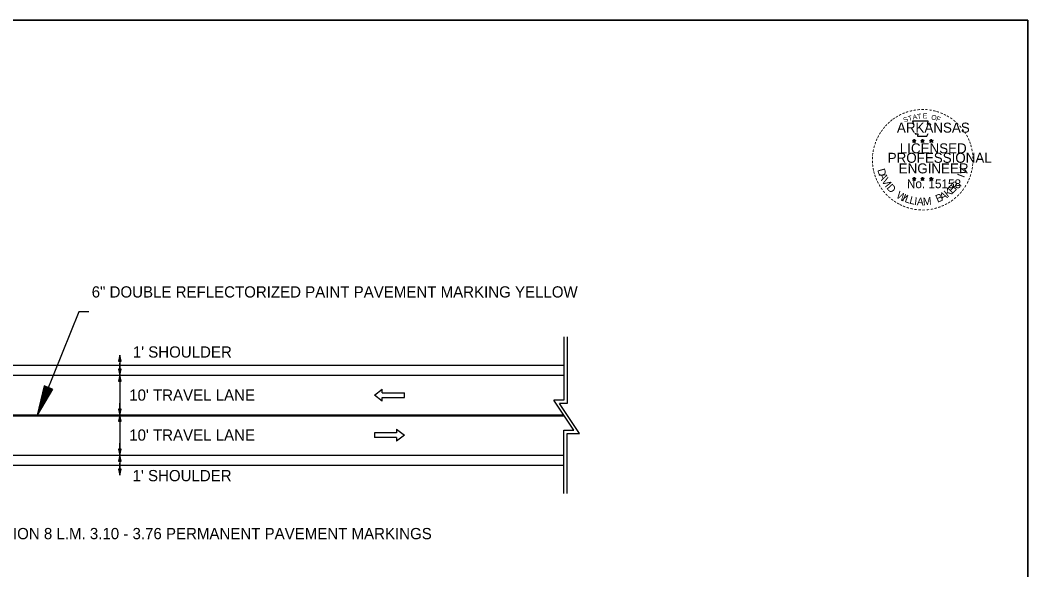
# Model space of a CAD drawing. Extents: x 1372926 to 1373096, y 381240 to 381790.
# Drawn here: x 1372995.2 to 1373096, y 381515.2 to 381570.2 of the extents above; entities that cross this region are included whole.
import ezdxf

# ---------------------------------------------------------------- set-up
doc = ezdxf.new("R2010")
doc.units = 0
for name, color, linetype in [('Default', 7, 'Continuous'), ('DSN_DRFT_Junk-No-Plot', 7, 'Continuous'), ('R_Draft', 7, 'Continuous'), ('SHET_Border-Text', 7, 'Continuous')]:
    doc.layers.add(name, color=color, linetype=linetype)

msp = doc.modelspace()

# ---------------------------------------------------------------- linework, layer by layer
at = {"layer": 'Default'}
for p, q in [((1373001.06, 381541), (1372996.9, 381530.64)), ((1373002.06, 381541), (1373001.06, 381541)), ((1373049.57, 381538.48), (1373049.57, 381532.14)), ((1373049.91, 381538.48), (1373049.91, 381531.81)), ((1372997.6, 381533.6), (1372996.9, 381530.64)), ((1372998.44, 381533.26), (1372996.9, 381530.64)), ((1372997.67, 381533.57), (1372997.09, 381531.11)), ((1372998.37, 381533.29), (1372997.09, 381531.11)), ((1372997.75, 381533.54), (1372997.28, 381531.59)), ((1372998.3, 381533.32), (1372997.28, 381531.59)), ((1372997.82, 381533.51), (1372997.47, 381532.05)), ((1372998.23, 381533.35), (1372997.47, 381532.05)), ((1372998.44, 381533.26), (1372997.6, 381533.6)), ((1372997.89, 381533.48), (1372997.66, 381532.52)), ((1372998.16, 381533.37), (1372997.66, 381532.52)), ((1372997.96, 381533.46), (1372997.85, 381532.99)), ((1372998.09, 381533.4), (1372997.85, 381532.99)), ((1373030.65, 381532.64), (1373031.42, 381533.24)), ((1373031.42, 381532.04), (1373030.65, 381532.64)), ((1373031.42, 381532.87), (1373031.42, 381533.24)), ((1373031.42, 381532.87), (1373033.63, 381532.87)), ((1373033.63, 381532.42), (1373033.63, 381532.87)), ((1373031.42, 381532.42), (1373033.63, 381532.42)), ((1373031.42, 381532.04), (1373031.42, 381532.42)), ((1373049.57, 381532.14), (1373048.57, 381532.14)), ((1373050.57, 381529.14), (1373048.57, 381532.14)), ((1373051.13, 381528.81), (1373049.13, 381531.81)), ((1373049.91, 381531.81), (1373049.13, 381531.81)), ((1373032.85, 381528.87), (1373030.65, 381528.87)), ((1373030.65, 381528.87), (1373030.65, 381528.42)), ((1373032.85, 381529.24), (1373032.85, 381528.87)), ((1373032.85, 381529.24), (1373033.63, 381528.64)), ((1373033.63, 381528.64), (1373032.85, 381528.04)), ((1373049.57, 381522.81), (1373049.57, 381529.14)), ((1373049.57, 381529.14), (1373050.57, 381529.14)), ((1373049.91, 381522.81), (1373049.91, 381528.81)), ((1373049.91, 381528.81), (1373051.13, 381528.81)), ((1373032.85, 381528.42), (1373030.65, 381528.42)), ((1373032.85, 381528.42), (1373032.85, 381528.04))]:
    msp.add_line(p, q, dxfattribs=at)
msp.add_lwpolyline([(1372925.97, 381570.17), (1372925.97, 381460.17), (1373095.97, 381460.17), (1373095.97, 381570.17)], close=True, dxfattribs=at)
at = {"layer": 'DSN_DRFT_Junk-No-Plot'}
msp.add_line((1373005.17, 381536.64), (1373005.17, 381524.64), dxfattribs=at)
for points in [[(1372925.97, 381570.17), (1373095.97, 381570.17), (1373095.97, 381460.17), (1372925.97, 381460.17)], [(1372925.97, 381570.17), (1372925.97, 381460.17), (1373095.97, 381460.17), (1373095.97, 381570.17)]]:
    msp.add_lwpolyline(points, close=True, dxfattribs=at)
for points in [[(1373005.17, 381536.64), (1373005.05, 381536.04), (1373005.29, 381536.04), (1373005.17, 381536.64), (1373005.17, 381535.44)], [(1373005.17, 381534.64), (1373005.29, 381535.24), (1373005.05, 381535.24), (1373005.17, 381534.64), (1373005.17, 381535.84)], [(1373005.17, 381534.64), (1373005.05, 381534.04), (1373005.29, 381534.04), (1373005.17, 381534.64), (1373005.17, 381533.44)], [(1373005.17, 381530.64), (1373005.29, 381531.24), (1373005.05, 381531.24), (1373005.17, 381530.64), (1373005.17, 381531.84)], [(1373005.17, 381530.64), (1373005.05, 381530.04), (1373005.29, 381530.04), (1373005.17, 381530.64), (1373005.17, 381529.44)], [(1373005.17, 381526.64), (1373005.29, 381527.24), (1373005.05, 381527.24), (1373005.17, 381526.64), (1373005.17, 381527.84)], [(1373005.17, 381526.64), (1373005.05, 381526.04), (1373005.29, 381526.04), (1373005.17, 381526.64), (1373005.17, 381525.44)], [(1373005.17, 381524.64), (1373005.29, 381525.24), (1373005.05, 381525.24), (1373005.17, 381524.64), (1373005.17, 381525.84)]]:
    msp.add_lwpolyline(points, dxfattribs=at)
at = {"layer": 'R_Draft'}
for p, q in [((1372973.18, 381535.64), (1373049.57, 381535.64)), ((1372973.18, 381534.64), (1373049.57, 381534.64)), ((1372973.15, 381530.69), (1373049.54, 381530.69)), ((1372973.21, 381530.59), (1373049.61, 381530.59)), ((1372973.18, 381526.64), (1373049.57, 381526.64)), ((1372973.18, 381525.64), (1373049.57, 381525.64))]:
    msp.add_line(p, q, dxfattribs=at)
at = {"layer": 'SHET_Border-Text'}
for p, q in [((1373084.43, 381558.13), (1373084.6, 381558.07)), ((1373084.43, 381558.13), (1373084.56, 381558.11)), ((1373084.43, 381558.13), (1373084.55, 381558.07)), ((1373084.5, 381557.93), (1373084.6, 381558.07)), ((1373084.5, 381557.93), (1373084.56, 381558.05)), ((1373084.5, 381557.93), (1373084.6, 381558.03)), ((1373084.6, 381558.26), (1373084.58, 381558.13)), ((1373084.6, 381558.07), (1373084.6, 381558.26)), ((1373084.6, 381558.26), (1373084.63, 381558.13)), ((1373084.78, 381558.13), (1373084.6, 381558.07)), ((1373084.71, 381557.93), (1373084.6, 381558.07)), ((1373084.71, 381557.93), (1373084.6, 381558.03)), ((1373084.78, 381558.13), (1373084.63, 381558.11)), ((1373084.71, 381557.93), (1373084.64, 381558.07)), ((1373084.78, 381558.13), (1373084.67, 381558.08)), ((1373085.26, 381558.13), (1373085.44, 381558.07)), ((1373085.26, 381558.13), (1373085.39, 381558.11)), ((1373085.26, 381558.13), (1373085.38, 381558.07)), ((1373085.33, 381557.93), (1373085.44, 381558.07)), ((1373085.33, 381557.93), (1373085.39, 381558.05)), ((1373085.33, 381557.93), (1373085.44, 381558.03)), ((1373085.44, 381558.26), (1373085.42, 381558.13)), ((1373085.44, 381558.07), (1373085.44, 381558.26)), ((1373085.44, 381558.26), (1373085.46, 381558.13)), ((1373085.61, 381558.13), (1373085.44, 381558.07)), ((1373085.54, 381557.93), (1373085.44, 381558.07)), ((1373085.54, 381557.93), (1373085.44, 381558.03)), ((1373085.61, 381558.13), (1373085.47, 381558.11)), ((1373085.54, 381557.93), (1373085.48, 381558.07)), ((1373085.61, 381558.13), (1373085.51, 381558.08)), ((1373086.15, 381558.12), (1373086.32, 381558.07)), ((1373086.15, 381558.12), (1373086.27, 381558.1)), ((1373086.15, 381558.12), (1373086.26, 381558.06)), ((1373086.21, 381557.92), (1373086.32, 381558.07)), ((1373086.21, 381557.92), (1373086.28, 381558.04)), ((1373086.21, 381557.92), (1373086.32, 381558.03)), ((1373086.32, 381558.25), (1373086.3, 381558.12)), ((1373086.32, 381558.07), (1373086.32, 381558.25)), ((1373086.32, 381558.25), (1373086.34, 381558.13)), ((1373086.49, 381558.12), (1373086.32, 381558.07)), ((1373086.43, 381557.92), (1373086.32, 381558.07)), ((1373086.43, 381557.92), (1373086.32, 381558.03)), ((1373086.49, 381558.12), (1373086.35, 381558.1)), ((1373086.43, 381557.92), (1373086.36, 381558.07)), ((1373086.49, 381558.12), (1373086.39, 381558.07)), ((1373084.43, 381554.34), (1373084.6, 381554.29)), ((1373084.43, 381554.34), (1373084.55, 381554.32)), ((1373084.43, 381554.34), (1373084.55, 381554.28)), ((1373084.49, 381554.14), (1373084.6, 381554.29)), ((1373084.49, 381554.14), (1373084.56, 381554.26)), ((1373084.49, 381554.14), (1373084.6, 381554.25)), ((1373084.6, 381554.47), (1373084.58, 381554.34)), ((1373084.6, 381554.29), (1373084.6, 381554.47)), ((1373084.6, 381554.47), (1373084.63, 381554.35)), ((1373084.77, 381554.34), (1373084.6, 381554.29)), ((1373084.71, 381554.14), (1373084.6, 381554.29)), ((1373084.71, 381554.14), (1373084.6, 381554.25)), ((1373084.77, 381554.34), (1373084.63, 381554.32)), ((1373084.71, 381554.14), (1373084.64, 381554.28)), ((1373084.77, 381554.34), (1373084.67, 381554.29)), ((1373085.26, 381554.34), (1373085.44, 381554.29)), ((1373085.26, 381554.34), (1373085.39, 381554.32)), ((1373085.26, 381554.34), (1373085.38, 381554.28)), ((1373085.33, 381554.14), (1373085.44, 381554.29)), ((1373085.33, 381554.14), (1373085.39, 381554.26)), ((1373085.33, 381554.14), (1373085.43, 381554.25)), ((1373085.44, 381554.47), (1373085.42, 381554.34)), ((1373085.54, 381554.14), (1373085.43, 381554.25)), ((1373085.44, 381554.29), (1373085.44, 381554.47)), ((1373085.44, 381554.47), (1373085.46, 381554.35)), ((1373085.61, 381554.34), (1373085.44, 381554.29)), ((1373085.54, 381554.14), (1373085.44, 381554.29)), ((1373085.61, 381554.34), (1373085.47, 381554.32)), ((1373085.54, 381554.14), (1373085.47, 381554.28)), ((1373085.61, 381554.34), (1373085.51, 381554.29)), ((1373086.14, 381554.34), (1373086.32, 381554.28)), ((1373086.14, 381554.34), (1373086.27, 381554.32)), ((1373086.14, 381554.34), (1373086.26, 381554.28)), ((1373086.21, 381554.13), (1373086.32, 381554.28)), ((1373086.21, 381554.13), (1373086.27, 381554.26)), ((1373086.21, 381554.13), (1373086.32, 381554.24)), ((1373086.32, 381554.47), (1373086.3, 381554.34)), ((1373086.32, 381554.28), (1373086.32, 381554.47)), ((1373086.32, 381554.47), (1373086.34, 381554.34)), ((1373086.49, 381554.34), (1373086.32, 381554.28)), ((1373086.43, 381554.13), (1373086.32, 381554.28)), ((1373086.43, 381554.13), (1373086.32, 381554.24)), ((1373086.49, 381554.34), (1373086.35, 381554.31)), ((1373086.43, 381554.13), (1373086.36, 381554.28)), ((1373086.49, 381554.34), (1373086.39, 381554.29))]:
    msp.add_line(p, q, dxfattribs=at)
for points in [[(1373084.45, 381560.07), (1373084.58, 381559.66)], [(1373086.2, 381559.61), (1373086.28, 381559.75), (1373085.93, 381559.74), (1373086.01, 381560.07), (1373084.45, 381560.07)], [(1373084.7, 381558.86), (1373084.7, 381558.81), (1373084.98, 381558.8), (1373084.95, 381558.57), (1373085.88, 381558.57), (1373085.99, 381558.84)], [(1373084.6, 381558.26), (1373084.71, 381557.93), (1373084.43, 381558.13), (1373084.78, 381558.13), (1373084.5, 381557.93), (1373084.6, 381558.26)], [(1373085.44, 381558.26), (1373085.54, 381557.93), (1373085.26, 381558.13), (1373085.61, 381558.13), (1373085.33, 381557.93), (1373085.44, 381558.26)], [(1373086.32, 381558.25), (1373086.43, 381557.92), (1373086.15, 381558.12), (1373086.49, 381558.12), (1373086.21, 381557.92), (1373086.32, 381558.25)], [(1373084.6, 381554.47), (1373084.71, 381554.14), (1373084.43, 381554.34), (1373084.77, 381554.34), (1373084.49, 381554.14), (1373084.6, 381554.47)], [(1373085.44, 381554.47), (1373085.54, 381554.14), (1373085.26, 381554.34), (1373085.61, 381554.34), (1373085.33, 381554.14), (1373085.44, 381554.47)], [(1373086.32, 381554.47), (1373086.43, 381554.13), (1373086.14, 381554.34), (1373086.49, 381554.34), (1373086.21, 381554.13), (1373086.32, 381554.47)]]:
    msp.add_lwpolyline(points, dxfattribs=at)
for centre, radius in [((1373084.6, 381558.07), 0.0861), ((1373084.6, 381558.07), 0.0723), ((1373084.6, 381558.07), 0.0579), ((1373084.6, 381558.07), 0.0495), ((1373084.6, 381558.07), 0.0374), ((1373084.6, 381558.07), 0.0248), ((1373084.6, 381558.07), 0.0148), ((1373085.44, 381558.07), 0.0861), ((1373085.44, 381558.07), 0.0723), ((1373085.44, 381558.07), 0.0579), ((1373085.44, 381558.07), 0.0495), ((1373085.44, 381558.07), 0.0374), ((1373085.44, 381558.07), 0.0248), ((1373085.44, 381558.07), 0.0148), ((1373086.32, 381558.07), 0.0861), ((1373086.32, 381558.07), 0.0723), ((1373086.32, 381558.07), 0.0579), ((1373086.32, 381558.07), 0.0495), ((1373086.32, 381558.07), 0.0374), ((1373086.32, 381558.07), 0.0248), ((1373086.32, 381558.07), 0.0148), ((1373084.6, 381554.29), 0.0861), ((1373084.6, 381554.29), 0.0723), ((1373084.6, 381554.29), 0.0579), ((1373084.6, 381554.29), 0.0495), ((1373084.6, 381554.29), 0.0374), ((1373084.6, 381554.29), 0.0248), ((1373084.6, 381554.29), 0.0148), ((1373085.44, 381554.29), 0.0861), ((1373085.44, 381554.29), 0.0723), ((1373085.44, 381554.29), 0.0579), ((1373085.44, 381554.29), 0.0495), ((1373085.44, 381554.29), 0.0374), ((1373085.44, 381554.29), 0.0248), ((1373085.44, 381554.29), 0.0148), ((1373086.32, 381554.28), 0.0861), ((1373086.32, 381554.28), 0.0723), ((1373086.32, 381554.28), 0.0579), ((1373086.32, 381554.28), 0.0495), ((1373086.32, 381554.28), 0.0374), ((1373086.32, 381554.28), 0.0248), ((1373086.32, 381554.28), 0.0148)]:
    msp.add_circle(centre, radius, dxfattribs=at)

# ---------------------------------------------------------------- texts
at = {"layer": 'Default'}
msp.add_text('6" DOUBLE REFLECTORIZED PAINT PAVEMENT MARKING YELLOW', height=1.125, dxfattribs=at).set_placement((1373002.36, 381542.42))
at = {"layer": 'R_Draft'}
for s, p in [("1' SHOULDER", (1373006.47, 381536.41)), ("10' TRAVEL LANE", (1373006.11, 381532.1)), ("10' TRAVEL LANE", (1373006.11, 381528.1)), ("1' SHOULDER", (1373006.45, 381524.04)), ('HWY. 128 SECTION 8 L.M. 3.10 - 3.76 PERMANENT PAVEMENT MARKINGS', (1372983.2, 381518.24))]:
    msp.add_text(s, height=1.125, dxfattribs=at).set_placement(p)
at = {"layer": 'SHET_Border-Text'}
for s, height, rotation, p in [('-', 0.8, 24.3072, (1373083.51, 381560.5)), ('-', 0.8, 19.1761, (1373083.82, 381560.63)), ('-', 0.8, 13.6302, (1373084.2, 381560.75)), ('-', 0.8, 10.2193, (1373084.54, 381560.83)), ('-', 0.8, 5.8968, (1373084.9, 381560.89)), ('-', 0.8, 0.1862, (1373085.29, 381560.92)), ('E', 0.5, 0.8323, (1373085.47, 381560.34)), ('-', 0.8, 357.743, (1373085.65, 381560.92)), ('-', 0.8, 352.1617, (1373086.02, 381560.89)), ('-', 0.8, 347.2049, (1373086.38, 381560.83)), ('-', 0.8, 342.3362, (1373086.7, 381560.76)), ('-', 0.8, 337.8551, (1373087.07, 381560.64)), ('-', 0.8, 42.9622, (1373082.15, 381559.56)), ('-', 0.8, 38.9507, (1373082.36, 381559.77)), ('-', 0.8, 36.2317, (1373082.6, 381559.96)), ('-', 0.8, 34.0636, (1373082.89, 381560.15)), ('-', 0.8, 28.7918, (1373083.19, 381560.34)), ('S', 0.5, 21.594, (1373083.63, 381559.91)), ('T', 0.5, 16.4036, (1373084.08, 381560.07)), ('A', 0.5, 11.2132, (1373084.5, 381560.2)), ('T', 0.5, 6.0228, (1373084.92, 381560.28)), ('O', 0.5, 350.4515, (1373086.28, 381560.23)), ('F', 0.5, 340.0707, (1373086.75, 381560.12)), ('-', 0.8, 334.1211, (1373087.38, 381560.51)), ('-', 0.8, 329.6409, (1373087.67, 381560.37)), ('-', 0.8, 325.8627, (1373087.99, 381560.19)), ('-', 0.8, 320.5297, (1373088.3, 381559.97)), ('-', 0.8, 315.5786, (1373088.6, 381559.73)), ('-', 0.8, 58.0706, (1373081.35, 381558.53)), ('-', 0.8, 54.2325, (1373081.52, 381558.79)), ('-', 0.8, 50.6142, (1373081.72, 381559.08)), ('-', 0.8, 48.4231, (1373081.92, 381559.32)), ('-', 0.8, 309.8797, (1373088.88, 381559.45)), ('-', 0.8, 306.6522, (1373089.14, 381559.15)), ('-', 0.7, 303.6753, (1373089.39, 381558.87)), ('-', 0.8, 72.3945, (1373080.96, 381557.6)), ('-', 0.8, 67.7743, (1373081.07, 381557.92)), ('-', 0.8, 62.8713, (1373081.2, 381558.22)), ('-', 0.8, 299.6684, (1373089.55, 381558.57)), ('-', 0.8, 294.6628, (1373089.71, 381558.26)), ('-', 0.8, 290.5728, (1373089.84, 381557.97)), ('-', 0.8, 85.1863, (1373080.75, 381556.54)), ('-', 0.8, 81.2013, (1373080.79, 381556.89)), ('-', 0.8, 75.461, (1373080.86, 381557.25)), ('-', 0.8, 285.1233, (1373089.95, 381557.68)), ('-', 0.8, 280.5493, (1373090.05, 381557.31)), ('-', 0.8, 276.5962, (1373090.13, 381556.93)), ('-', 0.8, 94.1959, (1373080.76, 381555.83)), ('-', 0.8, 89.0622, (1373080.74, 381556.19)), ('-', 0.8, 263.5172, (1373090.17, 381555.92)), ('-', 0.8, 274.3301, (1373090.16, 381556.57)), ('-', 0.8, 269.9407, (1373090.18, 381556.25)), ('-', 0.8, 98.9479, (1373080.8, 381555.5)), ('-', 0.8, 101.7149, (1373080.86, 381555.13)), ('-', 0.8, 105.4578, (1373080.94, 381554.83)), ('D', 0.77, 286.2848, (1373080.91, 381555.2)), ('I', 0.77, 69.0301, (1373089.59, 381554.35)), ('V', 0.77, 72.6573, (1373089.7, 381554.62)), ('-', 0.8, 255.7626, (1373090.08, 381555.25)), ('-', 0.8, 260.9953, (1373090.14, 381555.59)), ('-', 0.8, 109.0874, (1373081.05, 381554.52)), ('-', 0.8, 114.0643, (1373081.18, 381554.22)), ('-', 0.8, 115.7289, (1373081.33, 381553.91)), ('A', 0.77, 292.7835, (1373081.05, 381554.7)), ('V', 0.77, 300.7936, (1373081.31, 381554.11)), ('I', 0.77, 308.3502, (1373081.63, 381553.59)), ('D', 0.77, 311.9774, (1373081.8, 381553.36)), ('R', 0.77, 50.3651, (1373088.77, 381553.11)), (',', 0.77, 57.4684, (1373089.13, 381553.55)), ('-', 0.8, 244.6197, (1373089.75, 381554.24)), ('-', 0.8, 247.8887, (1373089.88, 381554.55)), ('-', 0.8, 252.8681, (1373089.99, 381554.89)), ('-', 0.8, 120.4471, (1373081.51, 381553.62)), ('-', 0.8, 125.8934, (1373081.71, 381553.34)), ('-', 0.8, 130.7181, (1373081.94, 381553.06)), ('-', 0.8, 134.2238, (1373082.2, 381552.79)), ('W', 0.77, 328.0731, (1373082.74, 381552.47)), ('I', 0.77, 336.6877, (1373083.33, 381552.12)), ('B', 0.77, 22.8589, (1373086.94, 381551.9)), ('A', 0.77, 28.9042, (1373087.39, 381552.09)), ('K', 0.77, 36.9143, (1373087.95, 381552.41)), ('E', 0.77, 44.0175, (1373088.4, 381552.75)), ('-', 0.8, 231.2538, (1373089.14, 381553.25)), ('-', 0.8, 233.8452, (1373089.35, 381553.54)), ('-', 0.8, 239.0712, (1373089.55, 381553.86)), ('-', 0.8, 138.9338, (1373082.46, 381552.56)), ('-', 0.8, 144.6463, (1373082.74, 381552.35)), ('-', 0.8, 148.0898, (1373083.02, 381552.17)), ('-', 0.8, 151.5704, (1373083.31, 381552.01)), ('-', 0.8, 154.6002, (1373083.57, 381551.88)), ('L', 0.77, 340.3149, (1373083.6, 381552)), ('L', 0.77, 346.6625, (1373084.08, 381551.83)), ('I', 0.77, 353.0101, (1373084.58, 381551.71)), ('A', 0.77, 356.6373, (1373084.86, 381551.66)), ('M', 0.77, 4.6473, (1373085.51, 381551.64)), ('-', 0.8, 207.3568, (1373087.81, 381552.12)), ('-', 0.8, 212.2491, (1373088.09, 381552.29)), ('-', 0.8, 215.7363, (1373088.36, 381552.48)), ('-', 0.8, 221.0851, (1373088.63, 381552.72)), ('-', 0.8, 225.7653, (1373088.9, 381552.97)), ('-', 0.8, 158.5612, (1373083.88, 381551.76)), ('-', 0.8, 162.7983, (1373084.23, 381551.65)), ('-', 0.8, 167.5555, (1373084.59, 381551.57)), ('-', 0.8, 173.1155, (1373084.97, 381551.51)), ('-', 0.8, 176.5183, (1373085.35, 381551.49)), ('-', 0.8, 181.5918, (1373085.72, 381551.49)), ('-', 0.8, 185.8167, (1373086.12, 381551.53)), ('-', 0.8, 191.2858, (1373086.49, 381551.6)), ('-', 0.8, 195.4743, (1373086.85, 381551.7)), ('-', 0.8, 199.4643, (1373087.19, 381551.82)), ('-', 0.8, 204.2516, (1373087.5, 381551.96))]:
    msp.add_text(s, height=height, rotation=rotation, dxfattribs=at).set_placement(p)
for s, height, p in [('ARKANSAS', 1, (1373082.88, 381558.92)), ('LICENSED', 1, (1373083.17, 381556.85)), ('PROFESSIONAL', 1, (1373081.96, 381555.9)), ('ENGINEER', 1, (1373083.06, 381554.84)), ('No. 15158', 0.878, (1373083.88, 381553.36)), ('AAMU', 0.00001, (1373085.4, 381551.63))]:
    msp.add_text(s, height=height, dxfattribs=at).set_placement(p)

doc.saveas('drawing.dxf')
